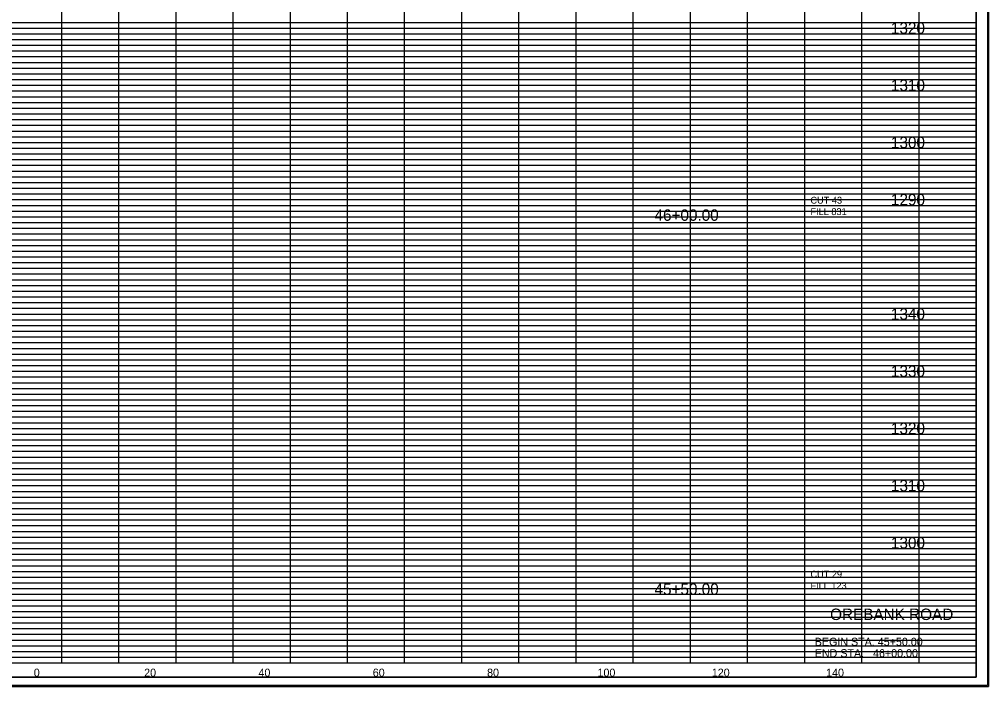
# Model space of a CAD drawing. Extents: x 980 to 1324, y 978 to 2847.
# Drawn here: x 1152.6 to 1322.2, y 1805.9 to 1922.5 of the extents above; entities that cross this region are included whole.
import ezdxf

# ---------------------------------------------------------------- set-up
doc = ezdxf.new("R2010")
doc.units = 0
for name, color, linetype in [('DESIGN - SHEET - Corner Text', 7, 'Continuous'), ('DESIGN - SHEET - Light Grid', 7, 'Continuous'), ('DESIGN - SHEET - Linework', 7, 'Continuous'), ('DESIGN - SHEET - Plot Shape', 7, 'Continuous'), ('DESIGN - TYPICAL - Text', 7, 'Continuous')]:
    doc.layers.add(name, color=color, linetype=linetype)

# ---------------------------------------------------------------- blocks, each defined once
blk = doc.blocks.new('XSTSHT')
at = {"layer": 'DESIGN - SHEET - Light Grid'}
for p, q in [((8, 11.2), (16, 11.2)), ((16, 11.2), (24, 11.2)), ((24, 11.2), (32, 11.2)), ((8, 11.1), (16, 11.1)), ((16, 11.1), (24, 11.1)), ((24, 11.1), (32, 11.1)), ((8, 10.9), (16, 10.9)), ((16, 10.9), (24, 10.9)), ((24, 10.9), (32, 10.9)), ((8, 10.8), (16, 10.8)), ((8, 10.7), (16, 10.7)), ((16, 10.8), (24, 10.8)), ((16, 10.7), (24, 10.7)), ((24, 10.8), (32, 10.8)), ((24, 10.7), (32, 10.7)), ((8, 10.6), (16, 10.6)), ((16, 10.6), (24, 10.6)), ((24, 10.6), (32, 10.6)), ((8, 10.5), (16, 10.5)), ((8, 10.4), (16, 10.4)), ((16, 10.5), (24, 10.5)), ((16, 10.4), (24, 10.4)), ((24, 10.5), (32, 10.5)), ((24, 10.4), (32, 10.4)), ((8, 10.3), (16, 10.3)), ((8, 10.2), (16, 10.2)), ((16, 10.3), (24, 10.3)), ((16, 10.2), (24, 10.2)), ((24, 10.3), (32, 10.3)), ((24, 10.2), (32, 10.2)), ((8, 10.1), (16, 10.1)), ((16, 10.1), (24, 10.1)), ((24, 10.1), (32, 10.1)), ((8, 9.9), (16, 9.9)), ((16, 9.9), (24, 9.9)), ((24, 9.9), (32, 9.9)), ((8, 9.8), (16, 9.8)), ((8, 9.7), (16, 9.7)), ((16, 9.8), (24, 9.8)), ((16, 9.7), (24, 9.7)), ((24, 9.8), (32, 9.8)), ((24, 9.7), (32, 9.7)), ((8, 9.6), (16, 9.6)), ((8, 9.5), (16, 9.5)), ((16, 9.6), (24, 9.6)), ((16, 9.5), (24, 9.5)), ((24, 9.6), (32, 9.6)), ((24, 9.5), (32, 9.5)), ((8, 9.4), (16, 9.4)), ((16, 9.4), (24, 9.4)), ((24, 9.4), (32, 9.4)), ((8, 9.3), (16, 9.3)), ((8, 9.2), (16, 9.2)), ((16, 9.3), (24, 9.3)), ((16, 9.2), (24, 9.2)), ((24, 9.3), (32, 9.3)), ((24, 9.2), (32, 9.2)), ((8, 9.1), (16, 9.1)), ((16, 9.1), (24, 9.1)), ((24, 9.1), (32, 9.1)), ((8, 8.9), (16, 8.9)), ((16, 8.9), (24, 8.9)), ((24, 8.9), (32, 8.9)), ((8, 8.8), (16, 8.8)), ((8, 8.7), (16, 8.7)), ((16, 8.8), (24, 8.8)), ((16, 8.7), (24, 8.7)), ((24, 8.8), (32, 8.8)), ((24, 8.7), (32, 8.7)), ((8, 8.6), (16, 8.6)), ((8, 8.5), (16, 8.5)), ((16, 8.6), (24, 8.6)), ((16, 8.5), (24, 8.5)), ((24, 8.6), (32, 8.6)), ((24, 8.5), (32, 8.5)), ((8, 8.4), (16, 8.4)), ((16, 8.4), (24, 8.4)), ((24, 8.4), (32, 8.4)), ((8, 8.3), (16, 8.3)), ((8, 8.2), (16, 8.2)), ((16, 8.3), (24, 8.3)), ((16, 8.2), (24, 8.2)), ((24, 8.3), (32, 8.3)), ((24, 8.2), (32, 8.2)), ((8, 8.1), (16, 8.1)), ((16, 8.1), (24, 8.1)), ((24, 8.1), (32, 8.1)), ((8, 7.9), (16, 7.9)), ((16, 7.9), (24, 7.9)), ((24, 7.9), (32, 7.9)), ((8, 7.8), (16, 7.8)), ((8, 7.7), (16, 7.7)), ((16, 7.8), (24, 7.8)), ((16, 7.7), (24, 7.7)), ((24, 7.8), (32, 7.8)), ((24, 7.7), (32, 7.7)), ((8, 7.6), (16, 7.6)), ((8, 7.5), (16, 7.5)), ((16, 7.6), (24, 7.6)), ((16, 7.5), (24, 7.5)), ((24, 7.6), (32, 7.6)), ((24, 7.5), (32, 7.5)), ((8, 7.4), (16, 7.4)), ((8, 7.3), (16, 7.3)), ((16, 7.4), (24, 7.4)), ((16, 7.3), (24, 7.3)), ((24, 7.4), (32, 7.4)), ((24, 7.3), (32, 7.3)), ((8, 7.2), (16, 7.2)), ((16, 7.2), (24, 7.2)), ((24, 7.2), (32, 7.2)), ((8, 7.1), (16, 7.1)), ((16, 7.1), (24, 7.1)), ((24, 7.1), (32, 7.1)), ((8, 6.9), (16, 6.9)), ((8, 6.8), (16, 6.8)), ((16, 6.9), (24, 6.9)), ((16, 6.8), (24, 6.8)), ((24, 6.9), (32, 6.9)), ((24, 6.8), (32, 6.8)), ((8, 6.7), (16, 6.7)), ((16, 6.7), (24, 6.7)), ((24, 6.7), (32, 6.7)), ((8, 6.6), (16, 6.6)), ((8, 6.5), (16, 6.5)), ((16, 6.6), (24, 6.6)), ((16, 6.5), (24, 6.5)), ((24, 6.6), (32, 6.6)), ((24, 6.5), (32, 6.5)), ((8, 6.4), (16, 6.4)), ((8, 6.3), (16, 6.3)), ((16, 6.4), (24, 6.4)), ((16, 6.3), (24, 6.3)), ((24, 6.4), (32, 6.4)), ((24, 6.3), (32, 6.3)), ((8, 6.2), (16, 6.2)), ((16, 6.2), (24, 6.2)), ((24, 6.2), (32, 6.2)), ((8, 6.1), (16, 6.1)), ((16, 6.1), (24, 6.1)), ((24, 6.1), (32, 6.1)), ((8, 5.9), (16, 5.9)), ((8, 5.8), (16, 5.8)), ((16, 5.9), (24, 5.9)), ((16, 5.8), (24, 5.8)), ((24, 5.9), (32, 5.9)), ((24, 5.8), (32, 5.8)), ((8, 5.7), (16, 5.7)), ((8, 5.6), (16, 5.6)), ((16, 5.7), (24, 5.7)), ((16, 5.6), (24, 5.6)), ((24, 5.7), (32, 5.7)), ((24, 5.6), (32, 5.6)), ((8, 5.5), (16, 5.5)), ((16, 5.5), (24, 5.5)), ((24, 5.5), (32, 5.5)), ((8, 5.4), (16, 5.4)), ((8, 5.3), (16, 5.3)), ((16, 5.4), (24, 5.4)), ((16, 5.3), (24, 5.3)), ((24, 5.4), (32, 5.4)), ((24, 5.3), (32, 5.3)), ((8, 5.2), (16, 5.2)), ((8, 5.1), (16, 5.1)), ((16, 5.2), (24, 5.2)), ((16, 5.1), (24, 5.1)), ((24, 5.2), (32, 5.2)), ((24, 5.1), (32, 5.1)), ((8, 4.9), (16, 4.9)), ((8, 4.8), (16, 4.8)), ((16, 4.9), (24, 4.9)), ((16, 4.8), (24, 4.8)), ((24, 4.9), (32, 4.9)), ((24, 4.8), (32, 4.8)), ((8, 4.7), (16, 4.7)), ((8, 4.6), (16, 4.6)), ((16, 4.7), (24, 4.7)), ((16, 4.6), (24, 4.6)), ((24, 4.7), (32, 4.7)), ((24, 4.6), (32, 4.6)), ((8, 4.5), (16, 4.5)), ((16, 4.5), (24, 4.5)), ((24, 4.5), (32, 4.5)), ((8, 4.4), (16, 4.4)), ((8, 4.3), (16, 4.3)), ((16, 4.4), (24, 4.4)), ((16, 4.3), (24, 4.3)), ((24, 4.4), (32, 4.4)), ((24, 4.3), (32, 4.3)), ((8, 4.2), (16, 4.2)), ((8, 4.1), (16, 4.1)), ((16, 4.2), (24, 4.2)), ((16, 4.1), (24, 4.1)), ((24, 4.2), (32, 4.2)), ((24, 4.1), (32, 4.1)), ((8, 3.9), (16, 3.9)), ((8, 3.8), (16, 3.8)), ((16, 3.9), (24, 3.9)), ((16, 3.8), (24, 3.8)), ((24, 3.9), (32, 3.9)), ((24, 3.8), (32, 3.8)), ((8, 3.7), (16, 3.7)), ((8, 3.6), (16, 3.6)), ((16, 3.7), (24, 3.7)), ((16, 3.6), (24, 3.6)), ((24, 3.7), (32, 3.7)), ((24, 3.6), (32, 3.6)), ((8, 3.5), (16, 3.5)), ((8, 3.4), (16, 3.4)), ((16, 3.5), (24, 3.5)), ((16, 3.4), (24, 3.4)), ((24, 3.5), (32, 3.5)), ((24, 3.4), (32, 3.4)), ((8, 3.3), (16, 3.3)), ((16, 3.3), (24, 3.3)), ((24, 3.3), (32, 3.3)), ((8, 3.2), (16, 3.2)), ((8, 3.1), (16, 3.1)), ((16, 3.2), (24, 3.2)), ((16, 3.1), (24, 3.1)), ((24, 3.2), (32, 3.2)), ((24, 3.1), (32, 3.1)), ((8, 2.9), (16, 2.9)), ((16, 2.9), (24, 2.9)), ((24, 2.9), (32, 2.9)), ((8, 2.8), (16, 2.8)), ((16, 2.8), (24, 2.8)), ((24, 2.8), (32, 2.8)), ((8, 2.7), (16, 2.7)), ((8, 2.6), (16, 2.6)), ((16, 2.7), (24, 2.7)), ((16, 2.6), (24, 2.6)), ((24, 2.7), (32, 2.7)), ((24, 2.6), (32, 2.6)), ((8, 2.5), (16, 2.5)), ((8, 2.4), (16, 2.4)), ((16, 2.5), (24, 2.5)), ((16, 2.4), (24, 2.4)), ((24, 2.5), (32, 2.5)), ((24, 2.4), (32, 2.4)), ((8, 2.3), (16, 2.3)), ((16, 2.3), (24, 2.3)), ((24, 2.3), (32, 2.3)), ((8, 2.2), (16, 2.2)), ((8, 2.1), (16, 2.1)), ((16, 2.2), (24, 2.2)), ((16, 2.1), (24, 2.1)), ((24, 2.2), (32, 2.2)), ((24, 2.1), (32, 2.1)), ((8, 1.9), (16, 1.9)), ((16, 1.9), (24, 1.9)), ((24, 1.9), (32, 1.9)), ((8, 1.8), (16, 1.8)), ((8, 1.7), (16, 1.7)), ((16, 1.8), (24, 1.8)), ((16, 1.7), (24, 1.7)), ((24, 1.8), (32, 1.8)), ((24, 1.7), (32, 1.7)), ((8, 1.6), (16, 1.6)), ((16, 1.6), (24, 1.6)), ((24, 1.6), (32, 1.6)), ((8, 1.5), (16, 1.5)), ((8, 1.4), (16, 1.4)), ((16, 1.5), (24, 1.5)), ((16, 1.4), (24, 1.4)), ((24, 1.5), (32, 1.5)), ((24, 1.4), (32, 1.4)), ((8, 1.3), (16, 1.3)), ((8, 1.2), (16, 1.2)), ((16, 1.3), (24, 1.3)), ((16, 1.2), (24, 1.2)), ((24, 1.3), (32, 1.3)), ((24, 1.2), (32, 1.2)), ((8, 1.1), (16, 1.1)), ((16, 1.1), (24, 1.1)), ((24, 1.1), (32, 1.1)), ((8, 0.9), (16, 0.9)), ((16, 0.9), (24, 0.9)), ((24, 0.9), (32, 0.9)), ((8, 0.8), (16, 0.8)), ((8, 0.7), (16, 0.7)), ((16, 0.8), (24, 0.8)), ((16, 0.7), (24, 0.7)), ((24, 0.8), (32, 0.8)), ((24, 0.7), (32, 0.7)), ((8, 0.6), (16, 0.6)), ((16, 0.6), (24, 0.6)), ((24, 0.6), (32, 0.6)), ((8, 0.5), (16, 0.5)), ((8, 0.4), (16, 0.4)), ((16, 0.5), (24, 0.5)), ((16, 0.4), (24, 0.4)), ((24, 0.5), (32, 0.5)), ((24, 0.4), (32, 0.4)), ((8, 0.3), (16, 0.3)), ((8, 0.2), (16, 0.2)), ((16, 0.3), (24, 0.3)), ((16, 0.2), (24, 0.2)), ((24, 0.3), (32, 0.3)), ((24, 0.2), (32, 0.2)), ((8, 0.1), (16, 0.1)), ((16, 0.1), (24, 0.1)), ((24, 0.1), (32, 0.1))]:
    blk.add_line(p, q, dxfattribs=at)
at = {"layer": 'DESIGN - SHEET - Linework'}
for p, q in [((32.217, 21.414), (32.217, -0.414)), ((16, 0), (16, 21)), ((17, 0), (17, 21)), ((18, 0), (18, 21)), ((19, 0), (19, 21)), ((20, 0), (20, 21)), ((21, 0), (21, 21)), ((22, 0), (22, 21)), ((23, 0), (23, 21)), ((24, 0), (24, 21)), ((25, 0), (25, 21)), ((26, 0), (26, 21)), ((27, 0), (27, 21)), ((28, 0), (28, 20)), ((29, 0), (29, 20)), ((30, 0), (30, 20)), ((31, 0), (31, 20)), ((0, 11), (32, 11)), ((0, 10), (32, 10)), ((0, 9), (32, 9)), ((0, 8), (32, 8)), ((0, 7), (32, 7)), ((0, 6), (32, 6)), ((0, 5), (32, 5)), ((0, 4), (32, 4)), ((0, 3), (32, 3)), ((0, 2), (32, 2)), ((0, 1), (32, 1)), ((-1.823, -0.414), (32.217, -0.414))]:
    blk.add_line(p, q, dxfattribs=at)
blk.add_lwpolyline([(0, 21), (0, 0), (32, 0), (32, 21), (0, 21)], dxfattribs=at)
at = {"layer": 'DESIGN - SHEET - Plot Shape'}
for points in [[(-1.803, 21.394), (32.197, 21.394), (32.197, -0.394), (-1.803, -0.394)], [(-0.85, 21), (32, 21), (32, -0.25), (-0.85, -0.25)]]:
    blk.add_lwpolyline(points, close=True, dxfattribs=at)

msp = doc.modelspace()

# ---------------------------------------------------------------- linework, layer by layer
at = {"layer": 'DESIGN - SHEET - Plot Shape'}
msp.add_lwpolyline([(991.5, 1807.5), (1320, 1807.5), (1320, 2020), (991.5, 2020)], close=True, dxfattribs=at)

# ---------------------------------------------------------------- block references
at = {"layer": 'DESIGN - SHEET - Plot Shape', "xscale": 10, "yscale": 10}
msp.add_blockref('XSTSHT', (1000, 1810), dxfattribs=at)

# ---------------------------------------------------------------- texts
at = {"layer": 'DESIGN - SHEET - Corner Text'}
for s, height, p in [('OREBANK ROAD', 2, (1294.44, 1817.5)), ('BEGIN STA. 45+50.00', 1.4, (1291.75, 1813)), ('END STA.   46+00.00', 1.4, (1291.75, 1811))]:
    msp.add_text(s, height=height, dxfattribs=at).set_placement(p)
at = {"layer": 'DESIGN - TYPICAL - Text'}
for s, height, p in [('     1320     ', 2, (1301.37, 1920)), ('     1310     ', 2, (1301.37, 1910)), ('     1300     ', 2, (1301.37, 1900)), ('CUT 43', 1.2, (1291, 1890.3)), ('     1290     ', 2, (1301.37, 1890)), ('     46+00.00     ', 2, (1260, 1887.3)), ('FILL 831', 1.2, (1291, 1888.3)), ('     1340     ', 2, (1301.37, 1870)), ('     1330     ', 2, (1301.37, 1860)), ('     1320     ', 2, (1301.37, 1850)), ('     1310     ', 2, (1301.37, 1840)), ('     1300     ', 2, (1301.37, 1830)), ('CUT 29', 1.2, (1291, 1824.91)), ('     45+50.00     ', 2, (1260, 1821.91)), ('FILL 123', 1.2, (1291, 1822.91)), ('     0     ', 1.4, (1152.51, 1807.6)), ('     0     ', 1.4, (1152.51, 1807.6)), ('     20     ', 1.4, (1171.82, 1807.6)), ('     40     ', 1.4, (1191.82, 1807.6)), ('     60     ', 1.4, (1211.82, 1807.6)), ('     80     ', 1.4, (1231.82, 1807.6)), ('     100     ', 1.4, (1251.14, 1807.6)), ('     120     ', 1.4, (1271.14, 1807.6)), ('     140     ', 1.4, (1291.14, 1807.6))]:
    msp.add_text(s, height=height, dxfattribs=at).set_placement(p)

doc.saveas('drawing.dxf')
